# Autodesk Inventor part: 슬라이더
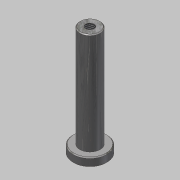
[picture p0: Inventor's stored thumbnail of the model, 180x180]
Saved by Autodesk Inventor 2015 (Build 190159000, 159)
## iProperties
Created: 2016-02
Part Number: 슬라이더
Material: 스테인리스강
Document SubType Name: Modeling
Designer: mduedu
Density: 8.08 g/cm^3
Appearance: 반광택
Mass: 65.4431 g
Surface Area: 33.4413 cm^2
Volume: 8.0994 cm^3
Author: mduedu
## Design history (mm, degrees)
sketch "스케치1"
  geometry: C1 r 10 at (0, 0); 1 further point
  constraints: 1 centre point, 1 coincident
  dimensions: "d0" = 20 diameter of C1
extrude "돌출1" new body sketch "스케치1" distance "d1" = 5; taper "d2" = 0 deg
sketch "스케치2"
  geometry: C1 r 6 at (0, 0); 1 further point
  constraints: 1 centre point, 1 coincident
  dimensions: "d3" = 12 diameter of C1
extrude "돌출2" join sketch "스케치2" distance "d4" = 60; taper "d5" = 0 deg
chamfer "모따기1" distance "d6" = 0.5; stored, may be unused: second distance "d7" = 2, angle "d8" = 45 deg
hole "구멍1" diameter "d11" = 4.917; stored, may be unused: countersink angle "d15" = 90 deg, drill point angle "d17" = 118 deg; dims "d9" = 10, "d10" = 10, "d12" = 10, "d13" = 4, "d14" = 2, "d16" = 12
chamfer "모따기2" distance "d18" = 0.5; stored, may be unused: second distance "d19" = 2, angle "d20" = 45 deg
node "솔리드1"
